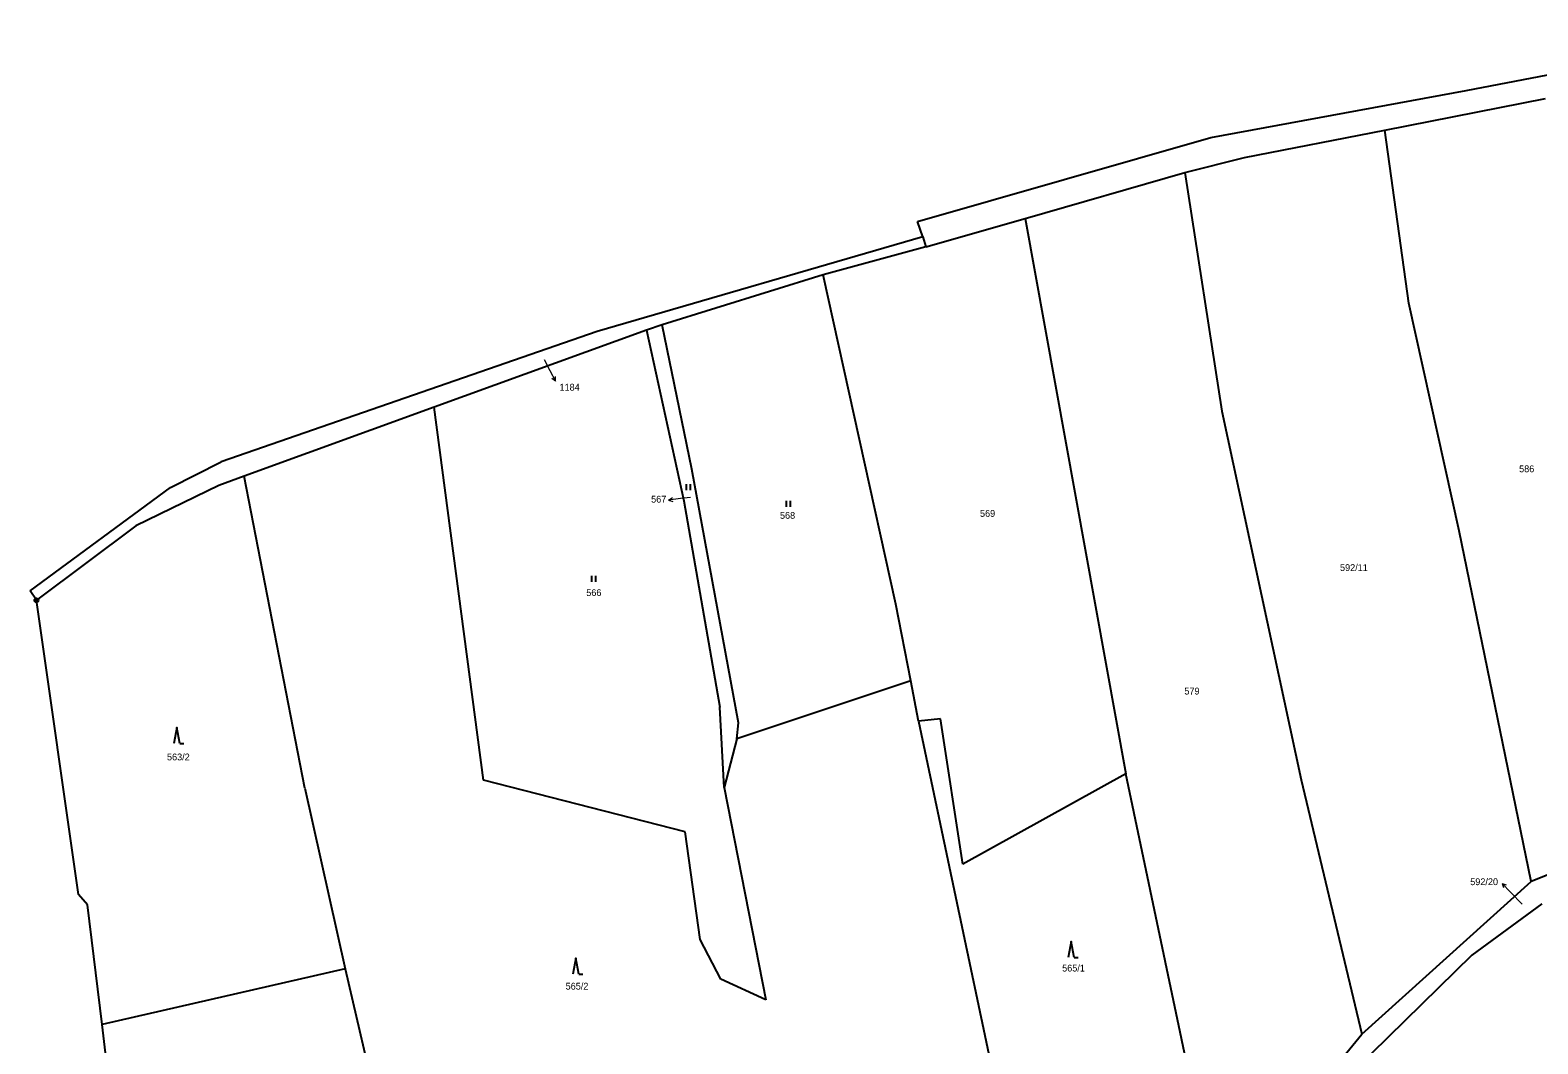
# Model space of a CAD drawing. Extents: x -765428 to -762163, y -1107632 to -1104975.
# Drawn here: x -765427.9 to -765051, y -1105512.2 to -1105258.8 of the extents above; entities that cross this region are included whole.
import ezdxf
from ezdxf.enums import TextEntityAlignment as Align

# ---------------------------------------------------------------- set-up
doc = ezdxf.new("R2010")
doc.units = 0
doc.header["$LTSCALE"] = 0.68
for name, color, linetype, lineweight in [('1', 7, 'Continuous', 25), ('3', 7, 'Continuous', 25), ('7', 7, 'Continuous', 13), ('8', 7, 'Continuous', 25)]:
    doc.layers.add(name, color=color, linetype=linetype, lineweight=lineweight)
doc.layers.add('2', color=7, linetype='Continuous')

msp = doc.modelspace()

# ---------------------------------------------------------------- linework, layer by layer
at = {"layer": '1'}
for p, q in [((-765068.87, -1105273.89), (-764989.99, -1105258.79)), ((-765132.75, -1105285.66), (-765068.87, -1105273.89)), ((-765089.2, -1105283.78), (-765049.09, -1105275.85)), ((-765206.01, -1105306.63), (-765132.75, -1105285.66)), ((-765124.32, -1105290.64), (-765089.2, -1105283.78)), ((-765083.23, -1105327.03), (-765089.2, -1105283.78)), ((-765139.23, -1105294.36), (-765124.32, -1105290.64)), ((-765179.14, -1105305.85), (-765139.23, -1105294.36)), ((-765139.23, -1105294.36), (-765129.95, -1105353.99)), ((-765203.97, -1105312.98), (-765179.14, -1105305.85)), ((-765179.14, -1105305.85), (-765154, -1105444.71)), ((-765204.75, -1105310.44), (-765206.01, -1105306.63)), ((-765204.75, -1105310.44), (-765286.08, -1105334.14)), ((-765203.97, -1105312.98), (-765229.63, -1105319.97)), ((-765204.75, -1105310.44), (-765203.97, -1105312.98)), ((-765229.63, -1105319.97), (-765269.86, -1105332.41)), ((-765211.47, -1105402.27), (-765229.63, -1105319.97)), ((-765070.64, -1105383.93), (-765083.23, -1105327.03)), ((-765286.08, -1105334.14), (-765380.12, -1105366.68)), ((-765273.82, -1105333.82), (-765326.86, -1105353.04)), ((-765269.86, -1105332.41), (-765273.82, -1105333.82)), ((-765273.82, -1105333.82), (-765264.43, -1105376.48)), ((-765262.42, -1105368.53), (-765269.86, -1105332.41)), ((-765326.86, -1105353.04), (-765374.34, -1105370.24)), ((-765314.51, -1105446.23), (-765326.86, -1105353.04)), ((-765129.95, -1105353.99), (-765110.12, -1105446.17)), ((-765392.74, -1105373.1), (-765380.12, -1105366.68)), ((-765250.83, -1105431.93), (-765262.42, -1105368.53)), ((-765427.86, -1105398.96), (-765392.74, -1105373.1)), ((-765380.67, -1105372.63), (-765401.41, -1105382.72)), ((-765374.34, -1105370.24), (-765380.67, -1105372.63)), ((-765359.18, -1105448.3), (-765374.34, -1105370.24)), ((-765264.43, -1105376.48), (-765255.43, -1105428.02)), ((-765401.41, -1105382.72), (-765426.29, -1105401.31)), ((-765052.63, -1105471.62), (-765070.64, -1105383.93)), ((-765426.29, -1105401.31), (-765427.86, -1105398.96)), ((-765415.79, -1105474.87), (-765426.29, -1105401.31)), ((-765207.73, -1105421.44), (-765211.47, -1105402.27)), ((-765207.73, -1105421.44), (-765251.23, -1105435.92)), ((-765205.8, -1105431.55), (-765207.73, -1105421.44)), ((-765254.36, -1105448.09), (-765255.43, -1105428.02)), ((-765251.23, -1105435.92), (-765250.83, -1105431.93)), ((-765200.3, -1105430.9), (-765205.8, -1105431.55)), ((-765205.8, -1105431.55), (-765187.33, -1105519.18)), ((-765194.7, -1105467.25), (-765200.3, -1105430.9)), ((-765251.23, -1105435.92), (-765254.36, -1105448.09)), ((-765154, -1105444.71), (-765194.7, -1105467.25)), ((-765137.28, -1105524.12), (-765154, -1105444.71)), ((-765359.18, -1105448.3), (-765349.1, -1105493.39)), ((-765264.14, -1105459.14), (-765314.51, -1105446.23)), ((-765254.36, -1105448.09), (-765243.92, -1105501.17)), ((-765110.12, -1105446.17), (-765094.97, -1105509.72)), ((-765260.36, -1105486.12), (-765264.14, -1105459.14)), ((-765037.34, -1105465.49), (-765052.63, -1105471.62)), ((-765094.97, -1105509.72), (-765052.63, -1105471.62)), ((-765413.51, -1105477.41), (-765415.79, -1105474.87)), ((-765409.9, -1105507.33), (-765413.51, -1105477.41)), ((-765049.99, -1105477.16), (-765067.45, -1105490.03)), ((-765255.18, -1105495.99), (-765260.36, -1105486.12)), ((-765067.45, -1105490.03), (-765092.55, -1105514.63)), ((-765349.1, -1105493.39), (-765409.9, -1105507.33)), ((-765349.1, -1105493.39), (-765343.62, -1105517.08)), ((-765243.92, -1105501.17), (-765255.18, -1105495.99)), ((-765401.49, -1105576.88), (-765409.9, -1105507.33)), ((-765129.16, -1105551.5), (-765094.97, -1105509.72))]:
    msp.add_line(p, q, dxfattribs=at)
at = {"layer": '3'}
for p, q in [((-765263.751, -1105373.8), (-765263.751, -1105372.3)), ((-765262.75, -1105373.8), (-765262.75, -1105372.3)), ((-765238.761, -1105377.91), (-765238.761, -1105376.41)), ((-765237.76, -1105377.91), (-765237.76, -1105376.41)), ((-765287.441, -1105396.69), (-765287.441, -1105395.19)), ((-765286.44, -1105396.69), (-765286.44, -1105395.19)), ((-765390.45, -1105437.14), (-765389.454, -1105437.14)), ((-765166.88, -1105490.61), (-765165.884, -1105490.61)), ((-765290.67, -1105494.78), (-765289.674, -1105494.78))]:
    msp.add_line(p, q, dxfattribs=at)
for points in [[(-765390.45, -1105437.14), (-765391.2, -1105433.14), (-765391.95, -1105437.14)], [(-765166.88, -1105490.61), (-765167.63, -1105486.61), (-765168.38, -1105490.61)], [(-765290.67, -1105494.78), (-765291.42, -1105490.78), (-765292.17, -1105494.78)]]:
    msp.add_lwpolyline(points, dxfattribs=at)
at = {"layer": '7'}
for p, q in [((-765296.521, -1105346.49), (-765296.549, -1105345.37)), ((-765268.259, -1105376.256), (-765267.204, -1105376.631)), ((-765059.915, -1105472.061), (-765059.579, -1105473.13))]:
    msp.add_line(p, q, dxfattribs=at)
for points in [[(-765299.34, -1105341.13), (-765297.93, -1105343.84), (-765296.521, -1105346.49), (-765297.433, -1105345.841)], [(-765262.83, -1105375.58), (-765265.28, -1105375.89), (-765268.259, -1105376.256), (-765267.326, -1105375.637)], [(-765054.9, -1105477.22), (-765057.83, -1105474.22), (-765059.915, -1105472.061), (-765058.859, -1105472.434)]]:
    msp.add_lwpolyline(points, dxfattribs=at)
at = {"layer": '8'}
for radius in [0.5, 0.0303]:
    msp.add_circle((-765426.29, -1105401.3099), radius, dxfattribs=at)

# ---------------------------------------------------------------- texts
at = {"layer": '2'}
for s, p in [('1184', (-765295.54, -1105348.895)), ('566', (-765288.85, -1105400.245))]:
    msp.add_text(s, height=1.7, dxfattribs=at).set_placement(p)
for s, p in [('586', (-765053.759, -1105369.295)), ('568', (-765238.529, -1105380.935)), ('569', (-765188.529, -1105380.445)), ('592/11', (-765096.95, -1105393.975)), ('579', (-765137.439, -1105424.855)), ('563/2', (-765390.81, -1105441.315)), ('565/1', (-765167.04, -1105494.095)), ('565/2', (-765291.16, -1105498.615))]:
    msp.add_text(s, height=1.7, dxfattribs=at).set_placement(p, align=Align.CENTER)
for s, p in [('567', (-765268.839, -1105376.885)), ('592/20', (-765060.929, -1105472.505))]:
    msp.add_text(s, height=1.7, dxfattribs=at).set_placement(p, align=Align.RIGHT)

doc.saveas('drawing.dxf')
